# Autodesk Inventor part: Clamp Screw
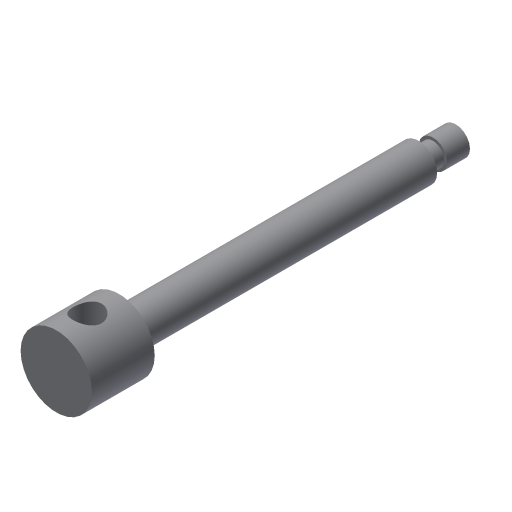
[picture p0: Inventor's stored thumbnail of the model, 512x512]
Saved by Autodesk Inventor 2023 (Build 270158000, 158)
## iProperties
Created: 2002-02
Part Number: Clamp Screw
Document SubType Name: Modeling
Designer: ***
Density: 1 g/cm^3
Material: Generic
Appearance: Default
Control State: 0
Master: False
Checked Out: False
Shininess: 77.0
Length Units: 11269
Angle Units: 11279
Time Units: 11290
Mass Units: 11283
Length Display Precision: 3
Angle Display Precision: 2
Density: 0.0
Volumn: 0.0
Area: 0.0
PropertySet Name: Model Information
Author: ***
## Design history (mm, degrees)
sketch "Sketch1"
  geometry: L1 (0, 140)-(5, 140); L2 (5, 140)-(5, 132); L3 (5, 132)-(4, 132); L4 (4, 132)-(4, 127); L5 (4, 127)-(6.5, 127); L6 (6.5, 127)-(6.5, 25); L7 (6.5, 25)-(4, 25); L8 (4, 25)-(4, 22); L9 (4, 22)-(12.5, 22); L10 (12.5, 22)-(12.5, 0); L11 (12.5, 0)-(0, 0); L12 (0, 0)-(0, 140)
  constraints: 24 end point, 10 parallel, 1 horizontal, 1 perpendicular
  dimensions: "d0" = 10 diameter of L2 L12; "d1" = 8 diameter of L4 L12; "d2" = 13 diameter of L6 L12; "d3" = 8 diameter of L7.end L12; "d4" = 25 diameter of L10 L12; "d5" = 3 distance from line of L7.end L9; "d6" = 8 distance of L1.end L2.end; "d7" = 13 vertical distance of L1.end L5.end; "d8" = 22 distance of L9.end L10.end; "d10" = 102 distance of L5.end L6.end
revolve "Revolution1" sketch "Sketch1" stored, may be unused: angle "d11" = 90 deg
sketch "Sketch3"
  geometry: L1 (-12.5, 0)-(12.5, 0) reference; C1 r 5 at (-0.113, 11)
  constraints: 1 centre point
  dimensions: "d13" = 10 diameter of C1; "d14" = 11 distance from line of L1 C1.centre
extrude "Extrusion1" cut sketch "Sketch3" extent not by distance; stored distance "d15" = 10; taper "d16" = 0 deg
body "Solid1"
